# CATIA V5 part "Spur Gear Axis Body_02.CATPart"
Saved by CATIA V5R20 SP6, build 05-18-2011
Part number: Spur Gear Axis Body_02
Bounding box of the stored display mesh (mm): x 0 to 11, y -10 to 10, z -10 to 10
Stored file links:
  E:\#01 CATIA Lecture Materials\#06 DMU\#10 Kinematics Joints\#002 Gear Joint(Spur Gear)\Spur Gear Axis Body_02.CATPart
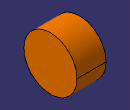
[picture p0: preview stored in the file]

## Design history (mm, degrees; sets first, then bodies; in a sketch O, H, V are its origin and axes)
Set1 "Reference Data"
  Point1 "Center Point": (0, 0, 0)
Body1 (main body)
  Sketch1 on yz-plane, origin (0, 0, 0), H (0, 1, 0), V (0, 0, 1)
    circle A1 centre (0, 0) radius 10
    radius A1 = 10
  Pad1: profile Sketch1, direction (1, 0, 0), length 11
